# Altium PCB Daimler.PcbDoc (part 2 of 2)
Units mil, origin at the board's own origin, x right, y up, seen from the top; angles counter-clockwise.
Board outline 11850 x 8035 mil, 2 copper layers (Top Layer, Bottom Layer); 112 components, 172 nets, 625 pads, 65 vias.
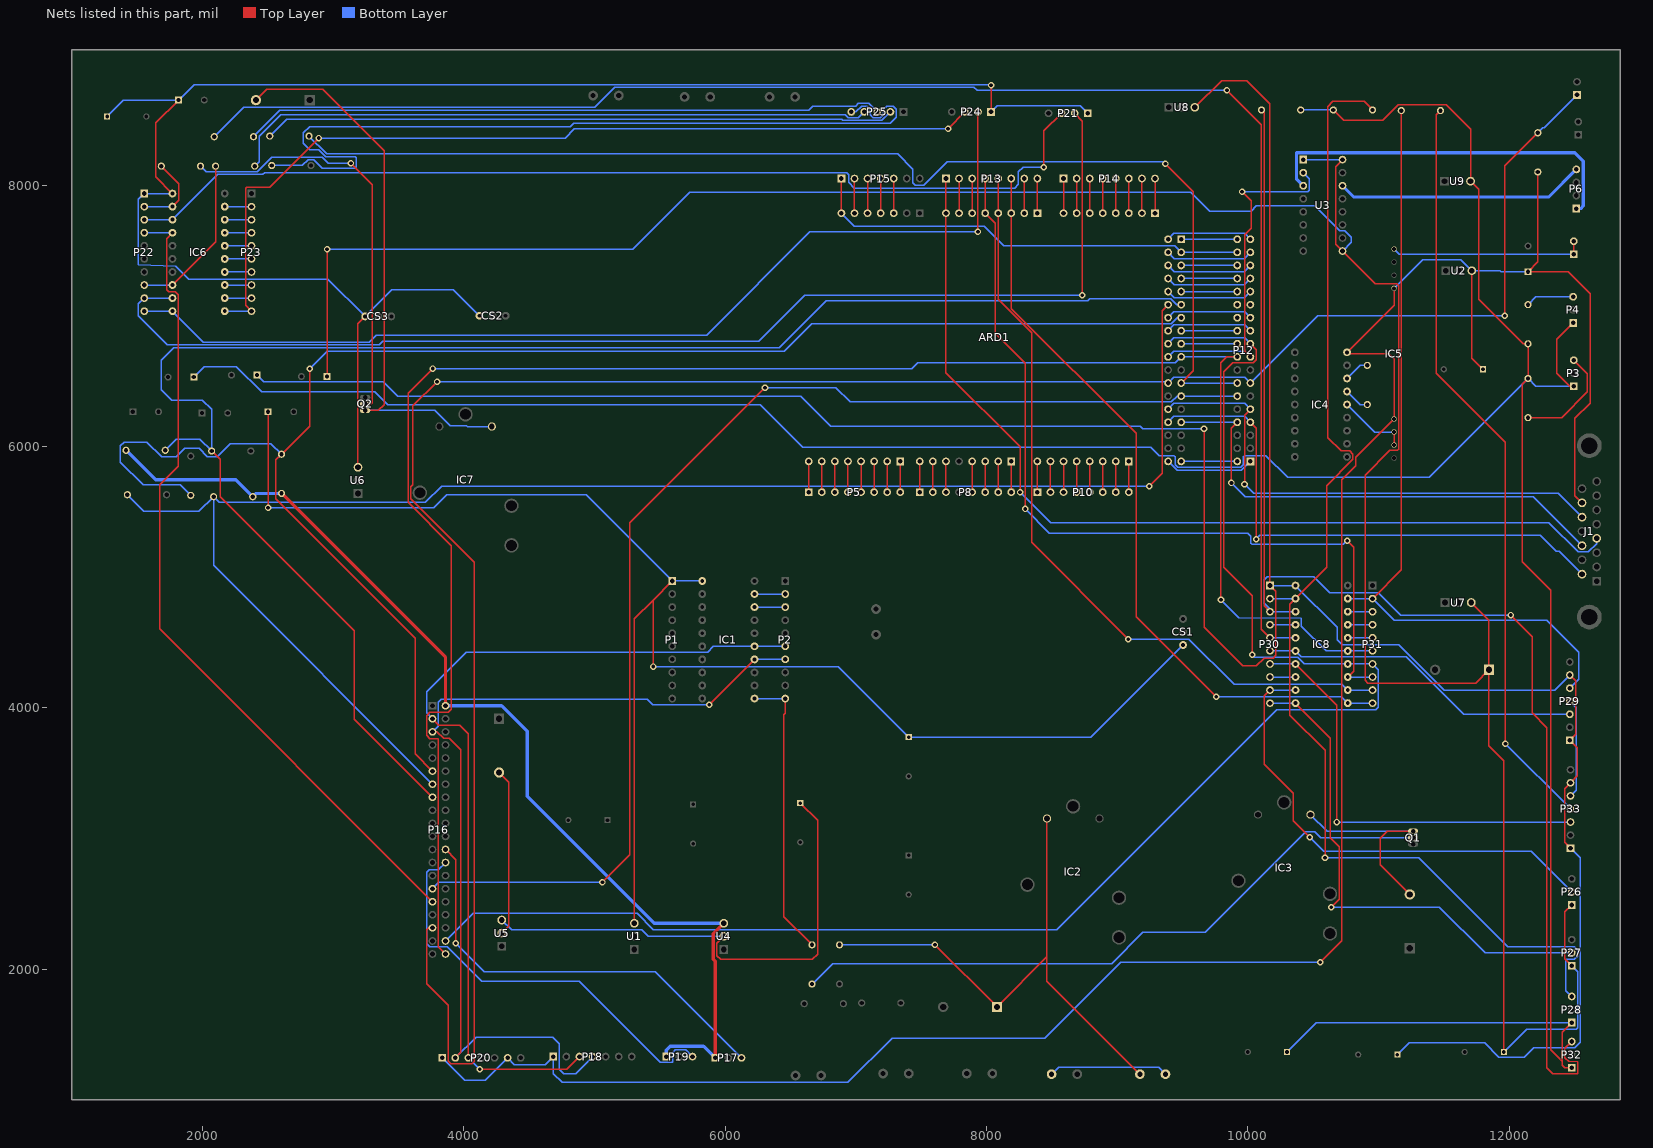
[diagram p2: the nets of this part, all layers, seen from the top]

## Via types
v1: diameter 50, hole 28, Top Layer to Bottom Layer, 57 vias
v2: diameter 196.85, hole 110.24, Top Layer to Bottom Layer, 4 vias
v3: diameter 118.11, hole 118.11, Top Layer to Bottom Layer, 4 vias

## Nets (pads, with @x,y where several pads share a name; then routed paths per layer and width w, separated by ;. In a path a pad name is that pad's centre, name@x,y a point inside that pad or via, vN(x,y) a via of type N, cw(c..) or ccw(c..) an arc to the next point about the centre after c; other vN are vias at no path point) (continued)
HS_18: IC1.18 P2.3 | length 235
  Bottom Layer w10: IC1.18@6225,4770 P2.3@6460,4770
HS_19: IC1.19 P2.2 | length 235
  Bottom Layer w10: IC1.19@6225,4870 P2.2@6460,4870
HSTOP_RELAY: IC1.11 P2.10 R1.2 | length 2213.2
  Top Layer w10: P2.10@6460,4070 6460,3956 6450,3946 6450,2400 R1.2@6665,2185
  Bottom Layer w10: IC1.11@6225,4070 P2.10@6460,4070
HSTOP_RELAY1_EN: D1.2 IC2.4 R2.2 ST2.2 | length 4194.5
  Top Layer w10: v1(7605.91,2185) D1.2@8080.91,1710 8463.23,2092.32 ; IC2.4@8463.23,3151.77 8463.23,2092.32 ; ST2.2@9174,1195 8463.23,1905.77 8463.23,2092.32
  Bottom Layer w10: R2.2@6875,2185 v1(7605.91,2185)
HSTOP_RELAY2_EN: D2.1 IC3.5 Q1.1 | length 1637
  Top Layer w10: D2.1@11240,2570.91 11012,2798.91 11012,3000 11067,3055 Q1.1@11265,3055
  Bottom Layer w10: IC3.5@10479.8,3181.77 10606.58,3055 Q1.1@11265,3055
JOYSTICK_IN: ARD1.32 P11.1 P12.13 P16.35 R8.2 | length 17177.8
  Top Layer w10: P16.35@3760,2315 3730,2315 3715,2300 3715,1888 3880,1723 3880,1295 3900,1275 4060,1275 4080,1295 4080,5114 3593.5,5600.5 3593.5,5690.5 3610,5707 3610,6310 v1(3795,6495) ; v1(11968,7001) 11968,8148 R8.2@12220,8400
  Bottom Layer w10: v1(3795,6495) 9380,6495 ARD1.32@9390,6485 9435,6530 9975,6530 P12.13@10020,6485 10536,7001 v1(11968,7001) ; R8.2@12220,8400 12258,8438 12268,8438 P11.1@12520,8690
LED_SINK: P6.4 U3.14 | length 1913.2
  Bottom Layer w25: U3.14@10725,7995 10811.24,7908.76 12303.76,7908.76 P6.4@12515,8120
LEFT_MARKER: ARD1.26 J1.9 P12.7 | length 4209.6
  Top Layer w10: P12.7@10020,6185 10064.53,6140.47 10064.53,5290.53 v1(10064,5290)
  Bottom Layer w10: ARD1.26@9390,6185 9435,6230 9975,6230 P12.7@10020,6185 ; v1(10064,5290) 10092.79,5318.79 12237.93,5318.79 12360,5196.72 12384.23,5196.72 J1.9@12558.11,5022.84
MAG_SENSOR_AN: ARD1.60 J1.4 P13.1 | length 7303.5
  Top Layer w10: P13.1@7690,8050 ARD1.60@7690,7785 7690,6564 8257,5997 v1(8257,5650)
  Bottom Layer w10: v1(8257,5650) 8491,5416 12305,5416 12529,5192 12606,5192 12669.92,5255.92 J1.4@12669.92,5295.47
MARKER_0: ARD1.43 P16.11 R9.2 R10.1 | length 12701.5
  Top Layer w10: v1(2821,6593) 2821,6156 R9.2@2605,5940 2562,5897 2562,5598 3628,4532 3628,3647 P16.11@3760,3515
  Bottom Layer w10: R10.1@1910,5625 1830,5705 1546,5705 1372,5879 1372,6005 1400,6033 1573.65,6033 1687.65,5919 1801,5919 1866,5984 1975,5984 2036.56,5922.44 2113,5922.44 2212.56,6022 2523,6022 R9.2@2605,5940 ; v1(2821,6593) 2956,6728 6453,6728 6663,6938 9413,6938 9460,6985 ARD1.43@9490,6985
MARKER_1: ARD1.44 P16.13 R11.2 R12.2 | length 12332.5
  Top Layer w10: v1(9245,5695) 9345,5795 9345,7040 ARD1.44@9390,7085
  Bottom Layer w10: R12.2@1425,5630 1552,5503 1973,5503 R11.2@2085,5615 ; P16.13@3760,3415 2085,5090 R11.2@2085,5615 ; v1(9245,5695) 3830,5695 3706,5571 2129,5571 R11.2@2085,5615
MARKER_2: ARD1.45 P16.15 R13.2 R14.2 | length 12790.2
  Top Layer w10: R14.2@2070,5965 2135,5900 2135,5615 3162,4588 3162,3913 P16.15@3760,3315
  Bottom Layer w10: R13.2@1715,5970 1801,6056 1979,6056 R14.2@2070,5965 2070,6284 2000,6354 1765,6354 1684,6435 1684,6660 1780,6756 6414,6756 6773.07,7115.07 8774.49,7115.07 8789.42,7130 9411,7130 9456,7085 ARD1.45@9490,7085
MEGA_0: ARD1.0 P8.8 | length 235
  Top Layer w10: P8.8@8190,5650 ARD1.0@8190,5885
MEGA_1: ARD1.1 P8.7 | length 235
  Top Layer w10: P8.7@8090,5650 ARD1.1@8090,5885
MEGA_2: ARD1.2 P8.6 | length 235
  Top Layer w10: P8.6@7990,5650 ARD1.2@7990,5885
MEGA_3: ARD1.3 P8.5 | length 235
  Top Layer w10: P8.5@7890,5650 ARD1.3@7890,5885
MEGA_7: ARD1.7 P8.1 | length 235
  Top Layer w10: P8.1@7490,5650 ARD1.7@7490,5885
MEGA_8: ARD1.8 P5.8 | length 235
  Top Layer w10: P5.8@7340,5650 ARD1.8@7340,5885
MEGA_9: ARD1.9 P5.7 | length 235
  Top Layer w10: P5.7@7240,5650 ARD1.9@7240,5885
MEGA_10: ARD1.10 P5.6 | length 235
  Top Layer w10: P5.6@7140,5650 ARD1.10@7140,5885
MEGA_11: ARD1.11 P5.5 | length 235
  Top Layer w10: P5.5@7040,5650 ARD1.11@7040,5885
MEGA_12: ARD1.12 P5.4 | length 235
  Top Layer w10: P5.4@6940,5650 ARD1.12@6940,5885
MEGA_13: ARD1.13 P5.3 | length 235
  Top Layer w10: P5.3@6840,5650 ARD1.13@6840,5885
MEGA_14: ARD1.14 P10.1 | length 235
  Top Layer w10: P10.1@8390,5650 ARD1.14@8390,5885
MEGA_15: ARD1.15 P10.2 | length 235
  Top Layer w10: P10.2@8490,5650 ARD1.15@8490,5885
MEGA_16: ARD1.16 P10.3 | length 235
  Top Layer w10: P10.3@8590,5650 ARD1.16@8590,5885
MEGA_17: ARD1.17 P10.4 | length 235
  Top Layer w10: P10.4@8690,5650 ARD1.17@8690,5885
MEGA_18: ARD1.18 P10.5 | length 235
  Top Layer w10: P10.5@8790,5650 ARD1.18@8790,5885
MEGA_19: ARD1.19 P10.6 | length 235
  Top Layer w10: P10.6@8890,5650 ARD1.19@8890,5885
MEGA_20: ARD1.20 P10.7 | length 235
  Top Layer w10: P10.7@8990,5650 ARD1.20@8990,5885
MEGA_21: ARD1.21 P10.8 | length 235
  Top Layer w10: P10.8@9090,5650 ARD1.21@9090,5885
MEGA_43: P12.24
MEGA_44: P12.25
MEGA_45: P12.26
MEGA_46: ARD1.46 P12.27 | length 669.8
  Bottom Layer w10: ARD1.46@9390,7185 9438,7137 9972,7137 P12.27@10020,7185
MEGA_47: ARD1.47 P12.28 | length 430
  Bottom Layer w10: ARD1.47@9490,7185 P12.28@9920,7185
MEGA_48: ARD1.48 P12.29 | length 669.8
  Bottom Layer w10: ARD1.48@9390,7285 9438,7237 9972,7237 P12.29@10020,7285
MEGA_49: ARD1.49 P12.30 | length 430
  Bottom Layer w10: ARD1.49@9490,7285 P12.30@9920,7285
MEGA_50: ARD1.50 P12.31 | length 669.8
  Bottom Layer w10: ARD1.50@9390,7385 9438,7337 9972,7337 P12.31@10020,7385
MEGA_51: ARD1.51 P12.32 | length 430
  Bottom Layer w10: ARD1.51@9490,7385 P12.32@9920,7385
MEGA_52: ARD1.52 P12.33 | length 669.8
  Bottom Layer w10: ARD1.52@9390,7485 9438,7437 9972,7437 P12.33@10020,7485
MEGA_53: ARD1.53 P12.34 P15.1 | length 3419.3
  Top Layer w10: ARD1.53@6890,7785 P15.1@6890,8050
  Bottom Layer w10: ARD1.53@6890,7785 6989.83,7685.17 7983.83,7685.17 8134,7535 9440,7535 ARD1.53@9490,7485 P12.34@9920,7485
MEGA_54: ARD1.54 P15.2 | length 265
  Top Layer w10: ARD1.54@6990,7785 P15.2@6990,8050
MEGA_55: ARD1.55 P15.3 | length 265
  Top Layer w10: ARD1.55@7090,7785 P15.3@7090,8050
MEGA_56: ARD1.56 P15.4 | length 265
  Top Layer w10: ARD1.56@7190,7785 P15.4@7190,8050
MEGA_57: ARD1.57 P15.5 | length 265
  Top Layer w10: ARD1.57@7290,7785 P15.5@7290,8050
MEGA_61: ARD1.61 P13.2 | length 265
  Top Layer w10: ARD1.61@7790,7785 P13.2@7790,8050
MEGA_62: ARD1.62 P13.3 | length 265
  Top Layer w10: ARD1.62@7890,7785 P13.3@7890,8050
MEGA_66: ARD1.66 P13.7 | length 265
  Top Layer w10: ARD1.66@8290,7785 P13.7@8290,8050
MEGA_67: ARD1.67 P13.8 | length 265
  Top Layer w10: ARD1.67@8390,7785 P13.8@8390,8050
MEGA_68: ARD1.68 P14.1 | length 265
  Top Layer w10: ARD1.68@8590,7785 P14.1@8590,8050
MEGA_69: ARD1.69 P14.2 | length 265
  Top Layer w10: ARD1.69@8690,7785 P14.2@8690,8050
MEGA_70: ARD1.70 P14.3 | length 265
  Top Layer w10: ARD1.70@8790,7785 P14.3@8790,8050
MEGA_71: ARD1.71 P14.4 | length 265
  Top Layer w10: ARD1.71@8890,7785 P14.4@8890,8050
MEGA_72: ARD1.72 P14.5 | length 265
  Top Layer w10: ARD1.72@8990,7785 P14.5@8990,8050
MEGA_73: ARD1.73 P14.6 | length 265
  Top Layer w10: ARD1.73@9090,7785 P14.6@9090,8050
MEGA_74: ARD1.74 P14.7 | length 265
  Top Layer w10: ARD1.74@9190,7785 P14.7@9190,8050
MEGA_75: ARD1.75 P14.8 | length 265
  Top Layer w10: ARD1.75@9290,7785 P14.8@9290,8050
MEGA_76: ARD1.76 P5.2 | length 235
  Top Layer w10: P5.2@6740,5650 ARD1.76@6740,5885
MEGA_77: ARD1.77 P5.1 | length 235
  Top Layer w10: P5.1@6640,5650 ARD1.77@6640,5885
MEGA_78: ARD1.78 P12.35 | length 667.3
  Bottom Layer w10: ARD1.78@9390,7585 9435,7630 9975,7630 P12.35@10020,7585
MEGA_79: ARD1.79 P12.36 | length 430
  Bottom Layer w10: ARD1.79@9490,7585 P12.36@9920,7585
MEGA_80: ARD1.80 P12.2 | length 430
  Bottom Layer w10: ARD1.80@9490,5885 P12.2@9920,5885
MEGA_81: ARD1.81 P12.1 | length 686.7
  Bottom Layer w10: ARD1.81@9390,5885 9458.44,5816.56 9951.56,5816.56 P12.1@10020,5885
MEGA_EN: ARD1.31 P12.12 P16.29 | length 9301.8
  Top Layer w10: v1(5061,2664) 5270,2873 5270,5415 v1(6305,6450)
  Bottom Layer w10: P16.29@3760,2615 3809,2664 v1(5061,2664) ; v1(6305,6450) 6847,6450 6957,6340 9415,6340 9460,6385 ARD1.31@9490,6385 P12.12@9920,6385
MEGA_LED: ARD1.33 P12.14 R19.1 | length 9088.6
  Top Layer w10: v1(9370,8164) 9584.06,7949.94 9584.06,6579.06 ARD1.33@9490,6485
  Bottom Layer w10: R19.1@2815,8375 2952,8238 7320,8238 7435,8123 7435,8019 7456.5,7997.5 7520.5,7997.5 7700,8177 9357,8177 v1(9370,8164) ; ARD1.33@9490,6485 P12.14@9920,6485
MEGA_VCC: C7.1 C8.1 IC4.18 IC5.4 IC5.5 J1.14 P18.1 P20.1 P20.6 R8.1 U2.2 | length 18276.5
  Top Layer w10: v1(10555,2053) 10720,2218 10720,5746.27 10825,5851.27 10825,5915 IC5.4@11120,6210 11120,6670 11080,6710 10770,6710 IC4.18@10760,6720 11120,7080 IC5.5@11120,7210 ; U2.2@11715,7345 11715,6675 C7.1@11800,6590 ; R8.1@12220,8100 12220,7411.57 C8.1@12145,7336.57 12453.43,7336.57 12621,7169 12621,6332 12504,6215 12504,5622.22 J1.14@12558.11,5568.11
  Bottom Layer w10: P20.1@3835,1320 4006,1149 4164,1149 P20.6@4335,1320 4387.5,1267.5 4622.5,1267.5 P18.1@4685,1330 4685,1200 4753,1132 6939,1132 7279,1472 8447,1472 9028,2053 v1(10555,2053) ; IC5.5@11120,7210 11340,7430 11630,7430 U2.2@11715,7345 11930,7345 11938.43,7336.57 C8.1@12145,7336.57
MHS1: IC6.19 P23.2 | length 205
  Bottom Layer w10: IC6.19@2170,7835 P23.2@2375,7835
MHS2: IC6.18 P23.3 | length 205
  Bottom Layer w10: IC6.18@2170,7735 P23.3@2375,7735
MHS3: IC6.13 P23.8 | length 205
  Bottom Layer w10: IC6.13@2170,7235 P23.8@2375,7235
MHS_HES1_IN: IC8.2 P28.3 P30.2 R20.2 | length 9437.1
  Top Layer w10: v1(10591,2851) 10591,3673 10320,3944 10320,4790 IC8.2@10365,4835 10604,5074 10604,5699 10805,5900 10805,5940 10780,5965 10715,5965 10612,6068 10612,8600 10652,8640 10890,8640 R20.2@10955,8575
  Bottom Layer w10: P30.2@10170,4835 IC8.2@10365,4835 ; v1(10591,2851) 11307,2851 11988,2170 12500,2170 12525,2145 12525,2099 12500,2074 12435,2074 12435,1835 P28.3@12480,1790
MHS_HES2_IN: IC8.3 P30.3 P32.3 R22.2 | length 10533.7
  Top Layer w10: R22.2@10105,8575 10125,8555 10125,4780 P30.3@10170,4735 ; v1(12012,4709) 12176,4545 12176,3961 12289,3848 12289,1244 12333,1200 12525,1200 12525,1291 12454.81,1292.5 12427.5,1319.81 12427.5,1392.5 P32.3@12480,1445
  Bottom Layer w10: P30.3@10170,4735 P30.3@10190,4735 ; IC8.3@10365,4735 10267,4735 P30.3@10190,4735 ; v1(12012,4709) 11171,4709 11000,4880 10627,4880 10503,5004 10149,5004 10125,4980 10125,4800 P30.3@10190,4735
MHS_SS_OUT1: ARD1.65 IC8.11 P13.6 P31.10 | length 5833.4
  Top Layer w10: P13.6@8190,8050 ARD1.65@8190,7785 8190,7055 9146,6099 9146,4695 v1(9758,4083)
  Bottom Layer w10: v1(9758,4083) 10717,4083 IC8.11@10765,4035 P31.10@10955,4035
MHS_SS_OUT2: ARD1.64 IC8.12 P13.5 P31.9 | length 5968.7
  Top Layer w10: P13.5@8090,8050 ARD1.64@8090,7785 8090,7126 8345,6871 8345,5265 v1(9085,4525)
  Bottom Layer w10: v1(9085,4525) 9550,4525 9895,4180 10720,4180 IC8.12@10765,4135 P31.9@10955,4135
MHS_SS_OUT3: ARD1.63 IC8.13 P13.4 P31.8 | length 6545.8
  Top Layer w10: P13.4@7990,8050 ARD1.63@7990,7785 8066,7709 8066,6866 8297,6635 v1(8297,5521) ; v1(10760,5278) 10810,5228 10810,4280 IC8.13@10765,4235
  Bottom Layer w10: v1(8297,5521) 8482,5336 10000,5336 10024,5312 10024,5260 10034,5250 10732,5250 v1(10760,5278) ; IC8.13@10765,4235 P31.8@10955,4235
MHS_US1_ECHO: IC6.3 P21.3 P22.3 | length 7709.2
  Top Layer w10: v1(8439,8136) 8439,8414 P21.3@8575,8550
  Bottom Layer w10: P22.3@1555,7735 IC6.3@1770,7735 2117.44,8082.44 2462.56,8082.44 2475.12,8095 6930,8095 6945,8080 6945,8020 6987.5,7977.5 8217.5,7977.5 8245,8005 8245,8101 8280,8136 v1(8439,8136)
MHS_US1_TRIGGER: IC6.9 P21.2 P22.9 | length 9261
  Top Layer w10: P21.2@8675,8550 8735,8490 8735,7157 v1(8734,7156)
  Bottom Layer w10: IC6.9@1770,7135 P22.9@1555,7135 1510,7090 1510,6999 1731,6778 3352,6778 3378,6804 6256,6804 6608,7156 v1(8734,7156)
MHS_US2_ECHO: IC6.11 P23.10 P24.3 | length 6910.4
  Top Layer w10: P23.10@2375,7035 2330,7080 2330,7974 2340,7984 2515,7984 v1(2891,8360) ; v1(7706,8431) P24.3@7835,8560
  Bottom Layer w10: IC6.11@2170,7035 P23.10@2375,7035 ; v1(2891,8360) 4776,8360 4847,8431 v1(7706,8431)
MHS_US2_TRIGGER: IC6.10 P22.10 P24.2 | length 7745.8
  Top Layer w10: v1(7935,7642) P24.2@7935,8560
  Bottom Layer w10: P22.10@1555,7035 IC6.10@1770,7035 2007,6798 3276,6798 3330,6852 5859,6852 6649,7642 v1(7935,7642)
MOTOR1_A: ARD1.39 P12.20 | length 430
  Bottom Layer w10: ARD1.39@9490,6785 P12.20@9920,6785
MOTOR1_B: ARD1.40 P12.21 | length 667.3
  Bottom Layer w10: ARD1.40@9390,6885 9435,6930 9975,6930 P12.21@10020,6885
MOTOR1_EN: ARD1.5 P8.3 | length 235
  Top Layer w10: P8.3@7690,5650 ARD1.5@7690,5885
MOTOR2_A: ARD1.41 P12.22 | length 430
  Bottom Layer w10: ARD1.41@9490,6885 P12.22@9920,6885
MOTOR2_B: ARD1.42 P12.23 | length 667.3
  Bottom Layer w10: ARD1.42@9390,6985 9435,7030 9975,7030 P12.23@10020,6985
MOTOR2_EN: ARD1.6 P8.2 | length 235
  Top Layer w10: P8.2@7590,5650 ARD1.6@7590,5885
MSP_SS0: ARD1.37 IC8.15 P12.18 P16.40 P31.6 | length 14460.5
  Top Layer w10: v1(3763,6596) 3573.5,6406.5 3573.5,5571.24 3905,5239.75 3905,3990 3880,3965 3740,3965 3715,3940 3715,3789 3740,3764 3801,3764 3805,3760 3805,2170 P16.40@3860,2115 ; v1(9795,4825) 9795,6640 9840,6685 P12.18@9920,6685
  Bottom Layer w10: v1(3763,6596) 7429,6596 7473.47,6640.47 9445.47,6640.47 ARD1.37@9490,6685 P12.18@9920,6685 ; v1(9795,4825) 9930,4690 10410,4685 10410,4625 10600,4435 IC8.15@10765,4435 P31.6@10955,4435
MSP_SS1: ARD1.38 IC8.14 P12.19 P16.38 P31.7 | length 12633.4
  Top Layer w10: P12.19@10020,6785 10064.53,6740.47 10064.53,6665 10040,6640.47 9885.47,6640.47 9815,6570 9815,5076 10035,4856 v1(10035,4405)
  Bottom Layer w10: P16.38@3860,2215 4071,2426 5326,2426 5451,2301 8539,2301 10223,3985 10980,3985 11000,4005 11000,4290 P31.7@10955,4335 IC8.14@10765,4335 10432,4335 10382,4385 10055,4385 v1(10035,4405) ; ARD1.38@9390,6785 9435,6830 9975,6830 P12.19@10020,6785
NetC10_1: C10.1 U4.3 U5.2 | length 3931.9
  Top Layer w10: U4.3@5990,2250 5937.5,2197.5 5937.5,2101 5964.5,2074 6668,2074 6708,2114 6708,3137 C10.1@6575,3270
  Bottom Layer w10: U5.2@4290,2375 4365,2300 5361,2300 5411,2250 U4.3@5990,2250
NetD3_1: D3.1 U5.3 | length 1281.3
  Top Layer w10: D3.1@4270,3504.09 4343,3431.09 4343,2328 U5.3@4290,2275
NetIC4_14: IC4.14 IC5.2 IC5.3 | length 547
  Top Layer w10: IC5.2@11120,6010 IC5.3@11120,6110
  Bottom Layer w10: IC4.14@10760,6320 10970,6110 IC5.3@11120,6110
NetIC4_15: IC4.15 R7.2 | length 196.4
  Bottom Layer w10: IC4.15@10760,6420 10860,6320 R7.2@10915,6320
NetIC4_16: IC4.16 R7.1 | length 196.4
  Bottom Layer w10: IC4.16@10760,6520 10860,6620 R7.1@10915,6620
NetIC5_8: IC5.8 P9.1 P9.2 | length 1491.6
  Top Layer w10: P9.1@12495,7470 P9.2@12495,7570
  Bottom Layer w10: IC5.8@11120,7510 11160,7470 P9.1@12495,7470
NetP3_3: P3.3 R5.1 | length 823.1
  Top Layer w10: R5.1@12145,6220 12403,6220 12600,6417 12600,6555 P3.3@12495,6660
NetP4_3: P4.3 R6.1 | length 369.9
  Bottom Layer w10: R6.1@12145,7085 12205,7145 P4.3@12490,7145
NetP25_2: P25.2 R19.2 | length 4832.9
  Bottom Layer w10: R19.2@2515,8375 2643,8503 6892.94,8503 6900.47,8495.47 7200.47,8495.47 P25.2@7265,8560
NetP25_3: P25.3 R18.2 | length 4907.2
  Bottom Layer w10: R18.2@2390,8370 2593,8573 6640,8573 6672,8605 7000.47,8605 7020,8624.53 7100.47,8624.53 P25.3@7165,8560
NetP25_4: P25.4 R17.2 | length 4969
  Bottom Layer w10: R17.2@2400,8145 2433,8178 2433,8373 2597,8537 6920,8537 6941.53,8515.47 7020.47,8515.47 P25.4@7065,8560
NetP25_5: P25.5 R16.2 | length 6437.5
  Bottom Layer w10: R16.2@2530,8150 2765,8150 2807.56,8192.56 2852.44,8192.56 2918,8127 3163,8127 3176,8140 3176,8209 3169,8216 2944,8216 2889,8271 2821,8271 2772,8320 2772,8400 2820,8448 4814,8448 4840,8474 7264,8474 7310,8520 7310,8580 7285,8605 7235,8605 7210,8580 7210,8540 7185.47,8515.47 7134.06,8515.47 7109.53,8540 7109.53,8580 7085,8604.53 7045.53,8604.53 7001,8560 P25.5@6965,8560
NetP29_4: P29.4 P33.5 | length 764.4
  Bottom Layer w10: P29.4@12465,4050 12515,4000 12515,3370 P33.5@12470,3325
NetP33_4: P33.4 R21.1 | length 5783.7
  Top Layer w10: R21.1@11475,8570 11443,8538 11443,6560 11972,6031 v1(11972,3723)
  Bottom Layer w10: v1(11972,3723) P33.4@12470,3225
NetQ1_2: Q1.2 R1.1 | length 5100.4
  Bottom Layer w10: R1.1@6665,1885 6822,2042 8958,2042 9196,2280 9676,2280 10445,3049 10514,3049 10558,3005 Q1.2@11265,3005
NetQ2_2: Q2.2 R15.1 | length 3192.2
  Top Layer w10: v1(3136,8167) 3300,8003 3300,6335 3290,6325 Q2.2@3245,6325
  Bottom Layer w10: R15.1@1985,8145 2027.56,8102.44 2420,8102.44 2530.12,8212.56 2916.44,8212.56 2962,8167 v1(3136,8167)
NetST1_2: ST1.2 ST2.1 | length 914.9
  Bottom Layer w10: ST1.2@8499,1195 8552,1248 9317,1248 ST2.1@9370,1195
RED: ARD1.36 P12.17 U3.2 | length 2672
  Top Layer w10: v1(9956,7949) 10025,7880 10025,7670 9975,7620 9975,6730 P12.17@10020,6685
  Bottom Layer w10: ARD1.36@9390,6685 9435,6730 9975,6730 P12.17@10020,6685 ; v1(9956,7949) 10460,7949 10470,7959 10470,8050 U3.2@10425,8095
RED_OP: P6.1 U3.3 | length 2902.2
  Bottom Layer w25: U3.3@10425,7995 10372,8048 10372,8248 12503,8248 12568,8183 12568,7840 12548,7820 P6.1@12515,7820
RIGHT_MARKER: ARD1.27 J1.11 P12.8 | length 3795.2
  Top Layer w10: v1(9875,5720) 9875,6140 P12.8@9920,6185
  Bottom Layer w10: ARD1.27@9490,6185 P12.8@9920,6185 ; v1(9875,5720) 9982,5613 12186.06,5613 J1.11@12558.11,5240.95
SAFETY_12: IC6.12 P23.9 | length 205
  Bottom Layer w10: IC6.12@2170,7135 P23.9@2375,7135
SAFETY_14: IC6.14 P23.7 | length 205
  Bottom Layer w10: IC6.14@2170,7335 P23.7@2375,7335
SAFETY_15: IC6.15 P23.6 | length 205
  Bottom Layer w10: IC6.15@2170,7435 P23.6@2375,7435
SAFETY_16: IC6.16 P23.5 | length 205
  Bottom Layer w10: IC6.16@2170,7535 P23.5@2375,7535
SAFETY_17: IC6.17 P23.4 | length 205
  Bottom Layer w10: IC6.17@2170,7635 P23.4@2375,7635
SAFETY_MSP_LED: IC6.8 P22.8 R17.1 | length 1261.7
  Top Layer w10: IC6.8@1770,7235 2100,7565 R17.1@2100,8145
  Bottom Layer w10: P22.8@1555,7235 IC6.8@1770,7235
SAFETY_RELAY: IC6.2 P22.2 R15.2 | length 600.8
  Top Layer w10: R15.2@1685,8145 1819,8011 1819,7884 IC6.2@1770,7835
  Bottom Layer w10: P22.2@1555,7835 IC6.2@1770,7835
SAFETY_RELAY_EN: D4.1 IC7.5 Q2.1 | length 4338.3
  Top Layer w10: D4.1@2409.09,8650 2493.09,8734 2919,8734 3390,8263 3390,6320 3345,6275 Q2.1@3245,6275
  Bottom Layer w10: Q2.1@3245,6275 3778.77,6275 3896.27,6157.5 4021.27,6157.5 4027,6151.77 IC7.5@4214.8,6151.77
SCL: IC1.14 P2.7 P16.5 P18.4 P20.2 | length 7118.5
  Top Layer w10: P16.5@3760,3815 3794.53,3815 3844.53,3765 3890,3765 3977,3678 3977,1362 P20.2@3935,1320 ; v1(5878,4023) IC1.14@6225,4370
  Bottom Layer w10: P16.5@3760,3815 3805,3860 3805,4040 3829,4064 5405,4064 5446,4023 v1(5878,4023) ; P20.2@3935,1320 4094,1479 4680,1479 4731,1428 4731,1232 4763,1200 4855,1200 P18.4@4985,1330 ; IC1.14@6225,4370 P2.7@6460,4370
SDA: IC1.15 P2.6 P16.3 P18.3 P20.3 | length 6844.2
  Top Layer w10: P16.3@3760,3915 3810,3865 3970,3865 4035,3800 P20.3@4035,1320 ; v1(4122,1233) 4788,1233 P18.3@4885,1330
  Bottom Layer w10: P16.3@3760,3915 3715,3960 3715,4123 4017,4425 5865,4425 5910,4470 IC1.15@6225,4470 P2.6@6460,4470 ; P20.3@4035,1320 v1(4122,1233)
SERVO1: IC8.9 P26.2 P30.9 | length 3663.8
  Top Layer w10: P30.9@10170,4135 10125,4090 10125,3569 10349,3345 10349,3134 v1(10474,3009)
  Bottom Layer w10: P30.9@10170,4135 IC8.9@10365,4135 ; v1(10474,3009) 10581,2902 12168,2902 P26.2@12480,2590
SERVO2: IC8.10 P27.2 P30.10 | length 3904.2
  Top Layer w10: IC8.10@10365,4035 10632,3768 10632,3004 10700,2936 10700,2534 v1(10640,2474)
  Bottom Layer w10: P30.10@10170,4035 IC8.10@10365,4035 ; v1(10640,2474) 11467,2474 11816,2125 P27.2@12480,2125
SOFTSTOP_MSP_LED: IC8.5 P30.5 R18.1 | length 12439.4
  Top Layer w10: v1(9840.59,8724.41) 10105,8460 10105,6610.44 10104,6609.44 10104,4601 P30.5@10170,4535
  Bottom Layer w10: R18.1@2090,8370 2315,8595 5003,8595 5157,8749 7904.5,8749 7929.09,8724.41 v1(9840.59,8724.41) ; P30.5@10170,4535 IC8.5@10365,4535
SS_4: IC8.4 P30.4 | length 195
  Bottom Layer w10: P30.4@10170,4635 IC8.4@10365,4635
SS_8: IC8.8 P30.8 | length 195
  Bottom Layer w10: P30.8@10170,4235 IC8.8@10365,4235
SS_16: IC8.16 P31.5 | length 190
  Bottom Layer w10: IC8.16@10765,4535 P31.5@10955,4535
SS_17: IC8.17 P31.4 | length 190
  Bottom Layer w10: IC8.17@10765,4635 P31.4@10955,4635
SS_18: IC8.18 P31.3 | length 190
  Bottom Layer w10: IC8.18@10765,4735 P31.3@10955,4735
START: P16.24 P17.3 | length 3300.6
  Top Layer w10: P16.24@3860,2915 3937,2838 v1(3937,2198)
  Bottom Layer w10: v1(3937,2198) 4156,1979 5466,1979 P17.3@6125,1320
STOP: P16.26 P19.3 | length 3238.4
  Bottom Layer w10: P16.26@3860,2815 3805,2760 3735,2760 3715,2740 3715,2195 3740,2170 3873,2170 4137,1906 4884.47,1906 5505,1285.47 5597.5,1285.47 5597.5,1360 5620,1382.5 5697.5,1382.5 P19.3@5750,1330
TO_MSP: IC6.4 P16.31 P22.4 | length 6344.3
  Top Layer w10: IC6.4@1770,7635 1725,7590 1725,7200 1740,7185 1790,7185 1815,7160 1815,5849 1672,5706 1672,4603 P16.31@3760,2515
  Bottom Layer w10: P22.4@1555,7635 IC6.4@1770,7635
TRACK_PRESENT: ARD1.28 J1.13 P12.9 | length 3948
  Top Layer w10: v1(9975,5710) 9975,6240 P12.9@10020,6285
  Bottom Layer w10: ARD1.28@9390,6285 9435,6330 9975,6330 P12.9@10020,6285 ; v1(9975,5710) 10045,5640 12377.17,5640 J1.13@12558.11,5459.06
US_AN_1: IC8.6 P29.3 P30.6 | length 2495.9
  Bottom Layer w10: P30.6@10170,4435 IC8.6@10365,4435 10410,4390 11211,4390 11651,3950 P29.3@12465,3950
US_AN_2: IC8.7 P30.7 P33.3 | length 3325.5
  Top Layer w10: IC8.7@10365,4335 10680,4020 v1(10680,3125)
  Bottom Layer w10: P30.7@10170,4335 IC8.7@10365,4335 ; v1(10680,3125) P33.3@12470,3125
US_SYNCH: IC8.19 P29.5 P31.2 R21.2 | length 6065.7
  Top Layer w10: P31.2@10955,4835 11175,5055 R21.2@11175,8570
  Bottom Layer w10: IC8.19@10765,4835 P31.2@10955,4835 11121.63,4668.37 12288.63,4668.37 12532,4425 12532,4217 P29.5@12465,4150
VCC_HES: C17.1 C18.1 P3.1 P4.1 P28.1 P32.1 R5.2 R6.2 R20.1 R22.1 U9.2 | length 23682.4
  Top Layer w10: R20.1@10655,8575 10733,8497 11034,8497 11150,8613 11518,8613 11705,8426 U9.2@11705,8030 11768,7967 11768,7125 12108,6785 R6.2@12145,6785 R5.2@12145,6520 12102,6477 12102,5117 12319,4900 12319,1384.09 12407.5,1295.59 ; P32.1@12480,1245 12427.5,1245 12407.5,1265 12407.5,1295.59 ; P28.1@12480,1590 12407.5,1517.5 12407.5,1295.59 ; P4.1@12490,6945 12365.47,6820.47 12365.47,6560 12465.47,6460 P3.1@12495,6460
  Bottom Layer w10: C18.1@1933.43,6530 2014.43,6611 2259,6611 2452,6418 3319,6418 3419,6318 6270,6318 6595,5993 9257.53,5993 9321,5929.53 9435,5929.53 9445,5919.53 9445,5860 9465,5840 9945,5840 9965,5860 9965,5920 9975,5930 10139,5930 10306,5763 11388,5763 R5.2@12145,6520 12205,6460 P3.1@12495,6460 ; C17.1@10300,1365 10525,1590 P28.1@12480,1590 ; R22.1@10405,8575 R20.1@10655,8575
VCC_MSP_HS: C1.1 C2.1 CS1.1 IC1.1 P1.1 U1.2 | length 12191.8
  Top Layer w10: v1(2501.57,5531) C2.1@2501.57,6265 ; U1.2@5305,2350 5305,4680 5449,4824 ; v1(5449,4315) 5449,4824 ; P1.1@5595,4970 5449,4824
  Bottom Layer w10: v1(2501.57,5531) 3771,5531 3869,5629 4936,5629 P1.1@5595,4970 IC1.1@5825,4970 ; v1(5449,4315) 6865,4315 C1.1@7405,3775 8800,3775 CS1.1@9505,4480
VCC_MSP_SAFETY: C11.1 C12.1 CS2.1 CS3.1 IC6.1 P21.1 P22.1 P24.1 U6.2 | length 13590.1
  Top Layer w10: IC6.1@1770,7935 1642,8063 1642,8475.43 C12.1@1816.57,8650 ; U6.2@3190,5840 3190,6940 CS3.1@3245,6995 ; P24.1@8035,8560 v1(8035,8765)
  Bottom Layer w10: C11.1@1270,8525 1395,8650 C12.1@1816.57,8650 1935.57,8769 8031,8769 v1(8035,8765) ; IC6.1@1770,7935 P22.1@1555,7935 1510,7890 1510,7389 1795,7380 1895,7280 2960,7280 CS3.1@3245,6995 3450,7200 3920,7200 CS2.1@4120,7000 ; P24.1@8035,8560 8081,8606 8719,8606 P21.1@8775,8550
VCC_MSP_SS: C15.1 C16.1 IC8.1 P29.1 P29.6 P30.1 P33.1 P33.6 U8.2 | length 21837
  Top Layer w10: U8.2@9595,8595 9799,8799 9992,8799 10170,8621 P30.1@10170,4935 10215,4890 10215,4400 10195,4380 10125,4380 10065,4320 9961,4320 9665,4616 v1(9665,6135) ; P29.6@12465,4250 12510,4205 12510,3795 P29.1@12465,3750 12522.5,3692.5 12522.5,3477.5 P33.6@12470,3425 12425,3380 12425,2970 P33.1@12470,2925
  Bottom Layer w10: C16.1@2418.43,6545 2470.43,6493 3383,6493 3494,6382 6580,6382 6808,6154 9177,6154 9196,6135 v1(9665,6135) ; P30.1@10170,4935 IC8.1@10365,4935 10683,4617 10683,4520 10723,4480 11155,4480 11502,4133 12348,4133 P29.6@12465,4250 ; C15.1@11145,1345 11235,1435 11812.38,1435 11921,1326.38 12114.38,1326.38 12187,1399 12504,1399 12545,1440 12545,2850 P33.1@12470,2925
VCC_PI: P16.2 P17.1 P19.1 R9.1 R11.1 R13.1 U4.2 | length 8147.1
  Top Layer w25: R9.1@2605,5640 3860,4385 P16.2@3860,4015 ; P17.1@5925,1320 5925,2059 5910,2074 5910,2270 U4.2@5990,2350
  Bottom Layer w25: R13.1@1415,5970 1641,5744 2256,5744 R11.1@2385,5615 2410,5640 R9.1@2605,5640 ; P16.2@3860,4015 4289,4015 4485,3819 4485,3321.93 5456.93,2350 U4.2@5990,2350 ; P19.1@5550,1330 5550,1380 5580,1410 5835,1410 P17.1@5925,1320
VCC_SERVO: C13.1 C14.1 D5.2 P26.1 P27.1 U3.1 U3.9 U3.16 U7.2 | length 20231.5
  Top Layer w10: C14.1@2953.43,6535 v1(2953.43,7508) ; U3.16@10725,8195 10672,8142 10672,7548 U3.9@10725,7495 10975,7245 11140,7245 11155,7230 11155,5980 11144,5969 11088,5969 10898,5779 10898,4209 10920,4187 11742.91,4187 D5.2@11845.91,4290 ; U7.2@11710,4805 11845.91,4669.09 D5.2@11845.91,4290 ; C13.1@11960,1365 11960,3595 11845.91,3709.09 D5.2@11845.91,4290 ; P27.1@12480,2025 12427,2078 12427,2437 P26.1@12480,2490
  Bottom Layer w10: v1(2953.43,7508) 5293,7508 5730,7945 9565.25,7945 9709.48,7800.77 10025,7800.77 10065.23,7841 10512,7841 10703,7650 10741,7650 10791,7600 10791,7561 U3.9@10725,7495 ; U3.1@10425,8195 U3.16@10725,8195 ; C13.1@11960,1365 12135,1540 12515,1540 12525,1550 12525,1980 P27.1@12480,2025
pads on no net: IC2.1 IC3.1 IC4.17 IC7.1 J1.2 J1.3 J1.6 J1.7 J1.10 J1.12 J1.15 J1.16 J1.17 P16.1 P16.6 P16.7 P16.8 P16.9 P16.10 P16.12 P16.14 P16.16 P16.17 P16.18 P16.19 P16.20 P16.21 P16.22 P16.23 P16.25 P16.27 P16.28 P16.30 P16.32 P16.34 P16.36 P16.37 P16.39 P18.5 P20.4 P29.2 P33.2
copper on no net:
  other v2: 1465,2006.54 3394.13,2006.54 1465,4290 3394.13,4290
  other v3: 6290,5885 9240,5885 6240,7785 9490,7785

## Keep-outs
Keep-Out Layer:
  the board outline again, w40

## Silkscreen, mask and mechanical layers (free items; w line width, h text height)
Top Overlay:
  text "+" at 4965,8825 h31.5
  text "-" at 5160,8820 h31.5
  text "22" at 9755,5970 h50
  text "23" at 10090,5965 h50
  text "1" at 5585,5040 h50
  text "20" at 6415,5040 h50
  text "10" at 5555,3950 h50
  text "11" at 6430,3950 h50
  text "gnd" at 6480,1385 h31.5
  text "12V" at 6700,1380 h31.5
